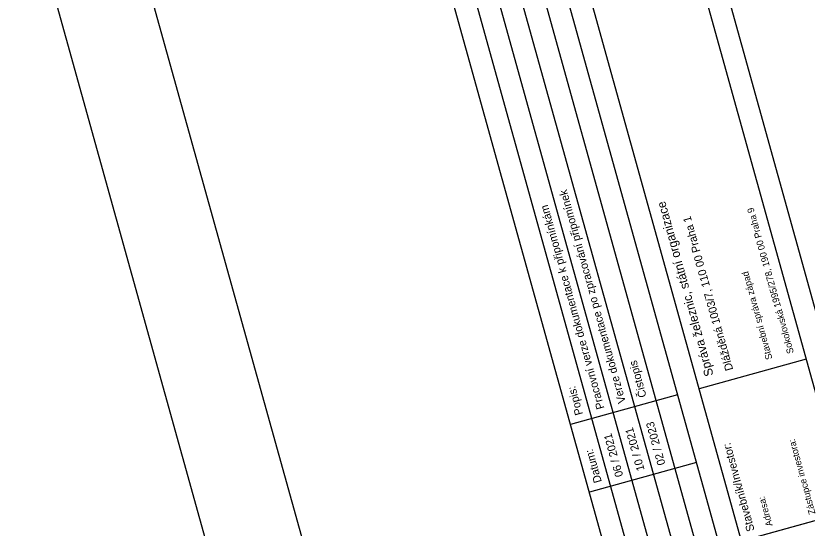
# Model space of a CAD drawing. Extents: x -821029 to -820632, y -1070881 to -1069931.
# Drawn here: x -821028.5 to -820939.6, y -1070045.8 to -1069988.2 of the extents above; entities that cross this region are included whole.
import ezdxf

# ---------------------------------------------------------------- set-up
doc = ezdxf.new("R2010")
doc.units = 0
doc.layers.add('Popisove_pole', color=7, linetype='Continuous')
doc.layers.add('Ram', color=7, linetype='Continuous')

msp = doc.modelspace()

# ---------------------------------------------------------------- linework, layer by layer
at = {"layer": 'Popisove_pole'}
for p, q in [((-820954.187, -1070049.303), (-820976.944, -1069967.406)), ((-820951.779, -1070048.634), (-820974.535, -1069966.737)), ((-820956.596, -1070049.972), (-820979.353, -1069968.075)), ((-820959.005, -1070050.642), (-820981.761, -1069968.745)), ((-820939.676, -1070026.823), (-820951.72, -1070030.169)), ((-820954.129, -1070030.838), (-820966.172, -1070034.185)), ((-820952.014, -1070038.45), (-820964.057, -1070041.797))]:
    msp.add_line(p, q, dxfattribs=at)
for points in [[(-820992.727, -1070060.012), (-821015.484, -1069978.115), (-820890.229, -1069943.311), (-820867.473, -1070025.208)], [(-820932.509, -1070043.279), (-820955.265, -1069961.382), (-820931.178, -1069954.689), (-820908.421, -1070036.586)], [(-820946.961, -1070047.295), (-820969.718, -1069965.398), (-820957.674, -1069962.052), (-820934.917, -1070043.949)], [(-820961.414, -1070051.311), (-820984.17, -1069969.414), (-820972.127, -1069966.067), (-820949.37, -1070047.965)]]:
    msp.add_lwpolyline(points, close=True, dxfattribs=at)
at = {"layer": 'Ram'}
msp.add_lwpolyline([(-821000.428, -1070071.476), (-821028.539, -1069970.309), (-820885.46, -1069930.552), (-820857.349, -1070031.719)], dxfattribs=at)

# ---------------------------------------------------------------- texts
at = {"layer": 'Popisove_pole'}
for s, height, p in [('Verze dokumentace po zpracování připomínek', 0.9, (-820959.95, -1070031.653)), ('Správa železnic, státní organizace', 1, (-820950.091, -1070028.602)), ('Pracovní verze dokumentace k připomínkám', 0.9, (-820962.358, -1070032.323)), ('Sokolovská 1995/278, 190 00 Praha 9', 0.75, (-820941.059, -1070026.093)), ('Dlážděná 1003/7, 110 00 Praha 1', 0.9, (-820947.874, -1070027.986)), ('Stavební správa západ', 0.75, (-820943.468, -1070026.762)), ('Čistopis', 0.9, (-820957.612, -1070031.004)), ('Popis:', 0.9, (-820964.767, -1070032.992)), ('02 / 2023', 0.9, (-820955.497, -1070038.615)), ('06 / 2021', 0.9, (-820960.243, -1070039.934)), ('10 / 2021', 0.9, (-820957.835, -1070039.265)), ('Zástupce investora:', 0.75, (-820938.628, -1070044.177)), ('Datum:', 0.9, (-820962.652, -1070040.604)), ('Stavebník/Investor:', 0.9, (-820945.469, -1070046.078)), ('Adresa:', 0.75, (-820943.446, -1070045.516))]:
    msp.add_text(s, height=height, rotation=105.52891, dxfattribs=at).set_placement(p)

doc.saveas('drawing.dxf')
